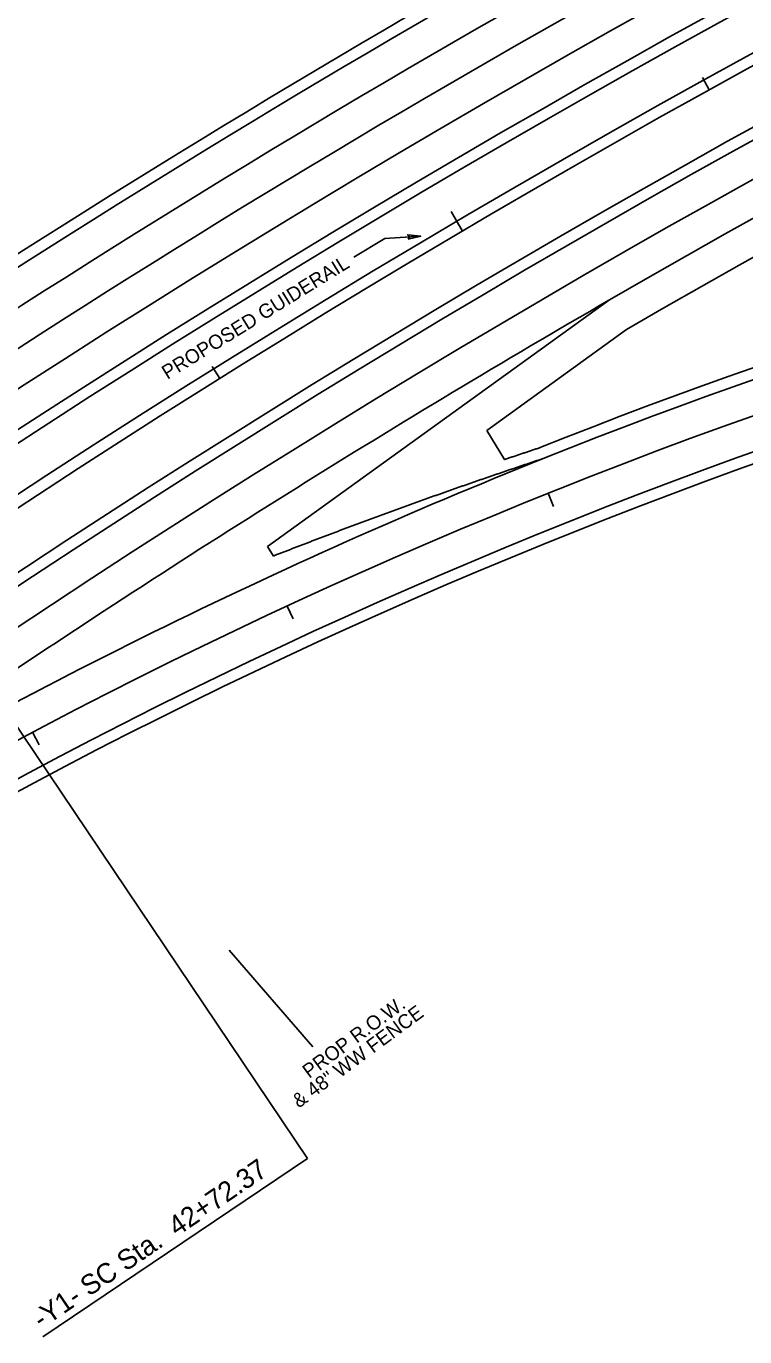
# Model space of a CAD drawing. Extents: x 2389099 to 2405615, y 552200 to 573532.
# Drawn here: x 2392734.5 to 2392987.4, y 553336.3 to 553797.6 of the extents above; entities that cross this region are included whole.
import ezdxf

# ---------------------------------------------------------------- set-up
doc = ezdxf.new("R2010")
doc.units = 0
for name, color, linetype in [('Prop Cable Guiderail Double Face', 7, 'Continuous'), ('Prop DSN Text', 7, 'Continuous'), ('Prop EOT', 7, 'Continuous'), ('Prop Horizontal Alignment', 7, 'Continuous'), ('Prop Horizontal Alignment Curve and Spiral Data', 7, 'Continuous'), ('Prop Horizontal Alignment Tick Large', 7, 'Continuous'), ('Prop Horizontal Alignment Tick Small', 7, 'Continuous'), ('Prop Lane Lines', 7, 'Continuous')]:
    doc.layers.add(name, color=color, linetype=linetype)

msp = doc.modelspace()

# ---------------------------------------------------------------- linework, layer by layer
at = {"layer": 'Prop Cable Guiderail Double Face'}
msp.add_arc((2394828.31, 550434.92), 3824, 87.04844, 123.9393, dxfattribs=at)
at = {"layer": 'Prop DSN Text'}
for p, q in [((2392849.81, 553716.34), (2392860.77, 553722.87)), ((2392860.77, 553722.87), (2392873.33, 553723.65)), ((2392835.34, 553438.41), (2392805.98, 553472.39))]:
    msp.add_line(p, q, dxfattribs=at)
msp.add_lwpolyline([(2392868.88, 553722.6), (2392873.33, 553723.65), (2392868.76, 553724.17), (2392869.38, 553723.41)], close=True, dxfattribs=at)
at = {"layer": 'Prop EOT'}
for p, q in [((2392939.74, 553701.24), (2392819.38, 553614.43)), ((2392945.75, 553690.85), (2392896.62, 553655.34)), ((2392896.62, 553655.34), (2392902.77, 553645.05)), ((2392819.38, 553614.43), (2392821.52, 553611.05))]:
    msp.add_line(p, q, dxfattribs=at)
for centre, radius, start, end in [((2394828.31, 550434.92), 3843, 59.69891, 123.9393), ((2394828.31, 550434.92), 3839, 59.69891, 123.9393), ((2394828.31, 550434.92), 3801, 59.69891, 123.9393), ((2394828.31, 550434.92), 3797, 59.69891, 123.9393), ((2394828.31, 550434.92), 3773, 89.80344, 120.03622), ((2394828.31, 550434.92), 3761, 90.54697, 120.03622), ((2394828.31, 550434.92), 3895, 115.09108, 123.9393), ((2394828.31, 550434.92), 3891, 115.09108, 123.9393), ((2393629.54, 551860.6), 1926, 73.14373, 111.77858), ((2393629.54, 551860.6), 1922, 73.14373, 111.77858), ((2393629.54, 551860.6), 1898, 73.14373, 120.73798), ((2393629.54, 551860.6), 1894, 73.14373, 120.73798)]:
    msp.add_arc(centre, radius, start, end, dxfattribs=at)
for points in [[(2392915.17, 553649.21), (2392914.52, 553648.99), (2392913.88, 553648.78), (2392913.23, 553648.56), (2392912.59, 553648.35), (2392911.94, 553648.13), (2392911.29, 553647.92), (2392910.64, 553647.7), (2392909.99, 553647.48), (2392909.35, 553647.27), (2392908.7, 553647.05), (2392908.06, 553646.83), (2392907.4, 553646.61), (2392906.76, 553646.4), (2392906.11, 553646.18), (2392905.46, 553645.96), (2392904.82, 553645.74), (2392904.17, 553645.52), (2392903.53, 553645.3), (2392902.88, 553645.08), (2392902.77, 553645.05)], [(2392916.44, 553645.42), (2392915.78, 553645.2), (2392915.14, 553644.99), (2392914.49, 553644.77), (2392913.85, 553644.56), (2392913.2, 553644.34), (2392912.56, 553644.13), (2392911.91, 553643.91), (2392911.26, 553643.69), (2392910.62, 553643.47), (2392909.97, 553643.26), (2392909.33, 553643.04), (2392908.68, 553642.82), (2392908.04, 553642.61), (2392907.39, 553642.39), (2392906.74, 553642.17), (2392906.1, 553641.95), (2392905.45, 553641.73), (2392904.81, 553641.52), (2392904.16, 553641.29), (2392903.52, 553641.08), (2392902.87, 553640.86), (2392902.23, 553640.64), (2392901.58, 553640.42), (2392900.94, 553640.2), (2392900.3, 553639.98), (2392899.65, 553639.76), (2392899.01, 553639.54), (2392898.36, 553639.31), (2392897.72, 553639.09), (2392897.07, 553638.87), (2392896.42, 553638.65), (2392895.78, 553638.43), (2392895.13, 553638.2), (2392894.5, 553637.98), (2392893.85, 553637.76), (2392893.21, 553637.54), (2392892.56, 553637.31), (2392891.91, 553637.09), (2392891.27, 553636.87), (2392890.63, 553636.64), (2392889.99, 553636.42), (2392889.34, 553636.19), (2392888.7, 553635.97), (2392888.05, 553635.75), (2392887.41, 553635.52), (2392886.77, 553635.3), (2392886.12, 553635.07), (2392885.48, 553634.85), (2392884.83, 553634.62), (2392884.2, 553634.39), (2392883.55, 553634.17), (2392882.9, 553633.94), (2392882.26, 553633.71), (2392881.62, 553633.48), (2392880.98, 553633.26), (2392880.33, 553633.03), (2392879.7, 553632.8), (2392879.05, 553632.57), (2392878.41, 553632.35), (2392877.77, 553632.12), (2392877.12, 553631.89), (2392876.48, 553631.66), (2392875.84, 553631.43), (2392875.2, 553631.2), (2392874.55, 553630.97), (2392873.92, 553630.74), (2392873.27, 553630.51), (2392872.62, 553630.28), (2392871.99, 553630.05), (2392871.34, 553629.82), (2392870.7, 553629.59), (2392870.06, 553629.36), (2392869.42, 553629.13), (2392868.78, 553628.89)], [(2392868.78, 553628.89), (2392868.13, 553628.66), (2392867.49, 553628.43), (2392866.85, 553628.2), (2392866.21, 553627.97), (2392865.57, 553627.73), (2392864.93, 553627.5), (2392864.29, 553627.27), (2392863.64, 553627.03), (2392863.01, 553626.8), (2392862.36, 553626.56), (2392861.73, 553626.33), (2392861.08, 553626.09), (2392860.44, 553625.86), (2392859.8, 553625.62), (2392859.16, 553625.39), (2392858.52, 553625.15), (2392857.88, 553624.92), (2392857.24, 553624.68), (2392856.6, 553624.45), (2392855.96, 553624.21), (2392855.32, 553623.97), (2392854.68, 553623.74), (2392854.04, 553623.5), (2392853.4, 553623.26), (2392852.76, 553623.03), (2392852.12, 553622.79), (2392851.48, 553622.55), (2392850.84, 553622.31), (2392850.2, 553622.07), (2392849.56, 553621.83), (2392848.92, 553621.59), (2392848.28, 553621.36), (2392847.64, 553621.11), (2392847.01, 553620.88), (2392846.36, 553620.64), (2392845.73, 553620.4), (2392845.09, 553620.16), (2392844.44, 553619.91), (2392843.81, 553619.67), (2392843.17, 553619.43), (2392842.53, 553619.19), (2392841.89, 553618.95), (2392841.26, 553618.71), (2392840.61, 553618.47), (2392839.97, 553618.22), (2392839.34, 553617.98), (2392838.7, 553617.74), (2392838.06, 553617.5), (2392837.42, 553617.25), (2392836.79, 553617.01), (2392836.15, 553616.77), (2392835.51, 553616.52), (2392834.87, 553616.28), (2392834.23, 553616.03), (2392833.6, 553615.79), (2392832.96, 553615.54), (2392832.32, 553615.3), (2392831.68, 553615.05), (2392831.05, 553614.81), (2392830.41, 553614.56), (2392829.77, 553614.32), (2392829.14, 553614.07), (2392828.5, 553613.82), (2392827.86, 553613.58), (2392827.22, 553613.33), (2392826.59, 553613.09), (2392825.95, 553612.84), (2392825.31, 553612.59), (2392824.68, 553612.34), (2392824.04, 553612.09), (2392823.41, 553611.85), (2392822.77, 553611.6), (2392821.49, 553611.1)]]:
    msp.add_spline(points, degree=3, dxfattribs=at)
at = {"layer": 'Prop Horizontal Alignment'}
for centre, radius, start, end in [((2394828.31, 550434.92), 3820, 59.69891, 123.9393), ((2393629.54, 551860.6), 1910, 73.14373, 120.73798)]:
    msp.add_arc(centre, radius, start, end, dxfattribs=at)
at = {"layer": 'Prop Horizontal Alignment Curve and Spiral Data'}
for p in [(2392696.39, 553602.86), (2392740.4, 553336.33)]:
    msp.add_line(p, (2392833.49, 553399.12), dxfattribs=at)
at = {"layer": 'Prop Horizontal Alignment Tick Large'}
msp.add_line((2392888.08, 553725.49), (2392884.01, 553732.38), dxfattribs=at)
at = {"layer": 'Prop Horizontal Alignment Tick Small'}
for p, q in [((2392974.87, 553775.15), (2392972.44, 553779.52)), ((2392802.61, 553673.58), (2392799.96, 553677.82)), ((2392918.14, 553633.17), (2392920, 553628.53)), ((2392826.35, 553593.51), (2392828.45, 553588.98)), ((2392736.77, 553549.11), (2392739.1, 553544.69))]:
    msp.add_line(p, q, dxfattribs=at)
at = {"layer": 'Prop Lane Lines'}
for centre, radius, start, end in [((2394828.31, 550434.92), 3855, 59.69891, 123.9393), ((2394828.31, 550434.92), 3785, 59.69891, 123.9393), ((2394828.31, 550434.92), 3879, 115.09108, 123.9393), ((2394828.31, 550434.92), 3867, 115.09108, 123.9393), ((2394828.31, 550434.92), 3773, 120.03622, 123.9393), ((2393629.54, 551860.6), 1922, 111.77858, 120.73798)]:
    msp.add_arc(centre, radius, start, end, dxfattribs=at)

# ---------------------------------------------------------------- texts
at = {"layer": 'Prop DSN Text'}
for s, rotation, p in [('PROPOSED GUIDERAIL', 31.6899, (2392784.2, 553673.08)), ('& 48" WW FENCE', 36.4467, (2392830.47, 553416.63)), ('PROP R.O.W.', 36.4467, (2392834.08, 553427.07))]:
    msp.add_text(s, height=5, rotation=rotation, dxfattribs=at).set_placement(p)
at = {"layer": 'Prop Horizontal Alignment Curve and Spiral Data'}
msp.add_text('-Y1- SC Sta.  42+72.37', height=7, rotation=34.2927, dxfattribs=at).set_placement((2392739.88, 553338.93))

doc.saveas('drawing.dxf')
